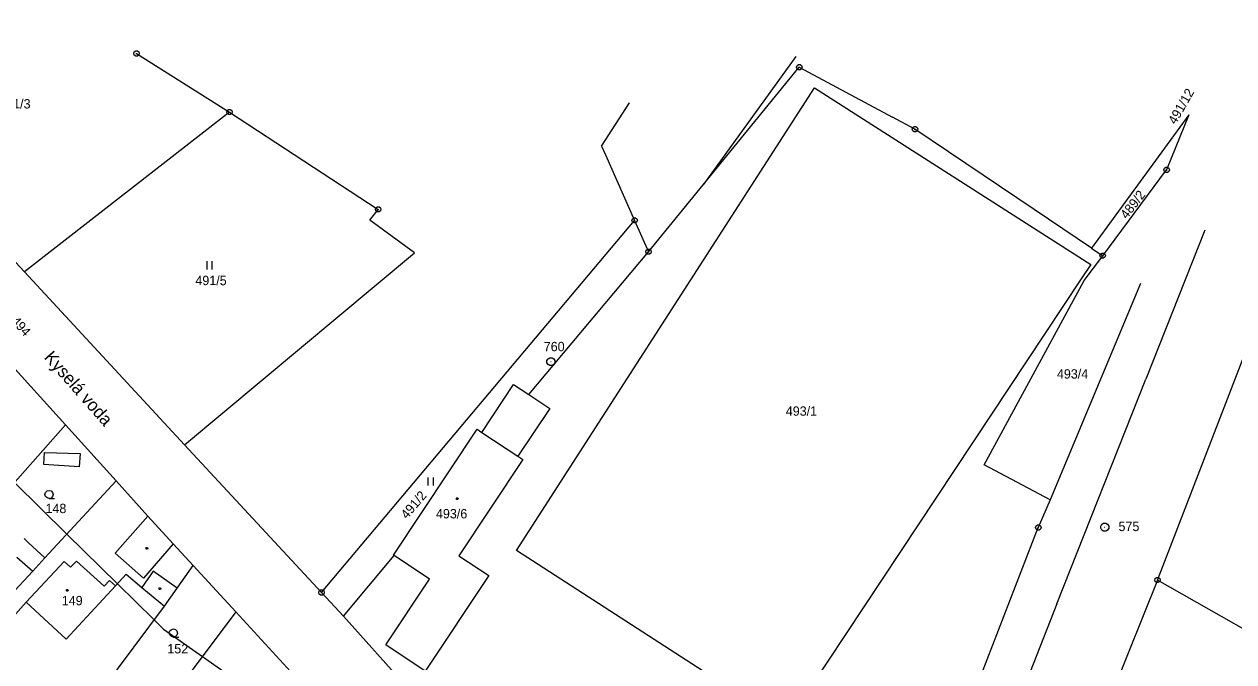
# Model space of a CAD drawing. Extents: x -755359 to -754474, y -1162585 to -1161655.
# Drawn here: x -754872 to -754652.1, y -1161783.9 to -1161668 of the extents above; entities that cross this region are included whole.
import ezdxf

# ---------------------------------------------------------------- set-up
doc = ezdxf.new("R2010")
doc.units = 0
for name, color, linetype in [('Vrstva 1', 7, 'Continuous'), ('Vrstva 11', 7, 'Continuous'), ('Vrstva 12', 7, 'Continuous'), ('Vrstva 2', 7, 'Continuous'), ('Vrstva 3', 7, 'Continuous'), ('Vrstva 4', 7, 'Continuous'), ('Vrstva 5', 7, 'Continuous'), ('Vrstva 6', 7, 'Continuous'), ('Vrstva 7', 7, 'Continuous'), ('Vrstva 8', 7, 'Continuous')]:
    doc.layers.add(name, color=color, linetype=linetype)

msp = doc.modelspace()

# ---------------------------------------------------------------- linework, layer by layer
at = {"layer": 'Vrstva 1'}
for p, q in [((-754871.95, -1161713.02), (-754913.71, -1161667.99)), ((-754851.55, -1161673.34), (-754851.55, -1161673.34)), ((-754851.55, -1161673.34), (-754834.66, -1161683.96)), ((-754731.71, -1161673.87), (-754748.55, -1161697.18)), ((-754748.55, -1161697.18), (-754731.08, -1161675.82)), ((-754731.71, -1161673.87), (-754731.71, -1161673.87)), ((-754731.08, -1161675.82), (-754714.14, -1161684.89)), ((-754767.01, -1161690.15), (-754761.96, -1161682.3)), ((-754761.96, -1161682.3), (-754761.96, -1161682.3)), ((-754834.66, -1161683.96), (-754871.95, -1161713.02)), ((-754834.66, -1161683.96), (-754807.62, -1161701.64)), ((-754660.25, -1161684.48), (-754677.94, -1161708.72)), ((-754660.25, -1161684.48), (-754664.3, -1161694.47)), ((-754660.25, -1161684.48), (-754660.25, -1161684.48)), ((-754714.14, -1161684.89), (-754714.14, -1161684.89)), ((-754710.05, -1161687.08), (-754714.14, -1161684.89)), ((-754703.93, -1161691.21), (-754710.05, -1161687.08)), ((-754767.01, -1161690.15), (-754766.3, -1161691.75)), ((-754703.93, -1161691.21), (-754703.93, -1161691.21)), ((-754688.38, -1161701.69), (-754703.93, -1161691.21)), ((-754766.3, -1161691.75), (-754761.02, -1161703.65)), ((-754766.3, -1161691.75), (-754766.3, -1161691.75)), ((-754675.92, -1161710.08), (-754664.3, -1161694.47)), ((-754664.3, -1161694.47), (-754664.3, -1161694.47)), ((-754758.49, -1161709.34), (-754748.55, -1161697.18)), ((-754809.17, -1161703.58), (-754807.62, -1161701.64)), ((-754688.38, -1161701.69), (-754688.38, -1161701.69)), ((-754677.94, -1161708.72), (-754688.38, -1161701.69)), ((-754817.93, -1161771.28), (-754761.02, -1161703.65)), ((-754801, -1161709.54), (-754809.17, -1161703.58)), ((-754761.02, -1161703.65), (-754758.49, -1161709.34)), ((-754677.94, -1161708.72), (-754677.94, -1161708.72)), ((-754677.94, -1161708.72), (-754675.92, -1161710.08)), ((-754842.82, -1161744.44), (-754801, -1161709.54)), ((-754780.24, -1161735.32), (-754758.49, -1161709.34)), ((-754679.27, -1161714.58), (-754675.92, -1161710.08)), ((-754842.82, -1161744.44), (-754871.95, -1161713.02)), ((-754665.97, -1161769.03), (-754644.01, -1161712.08)), ((-754697.48, -1161748.06), (-754679.27, -1161714.58)), ((-754669.05, -1161715.13), (-754685.45, -1161754.46)), ((-754669.05, -1161715.13), (-754669.05, -1161715.13)), ((-754873.65, -1161730.71), (-754864.46, -1161740.82)), ((-754788.78, -1161742.18), (-754783.01, -1161733.47)), ((-754783.01, -1161733.47), (-754780.24, -1161735.32)), ((-754780.24, -1161735.32), (-754776.44, -1161737.85)), ((-754776.44, -1161737.85), (-754782.27, -1161746.49)), ((-754878.05, -1161756.11), (-754864.46, -1161740.82)), ((-754864.46, -1161740.82), (-754855.27, -1161750.98)), ((-754804.85, -1161764.48), (-754789.63, -1161741.62)), ((-754789.63, -1161741.62), (-754788.78, -1161742.18)), ((-754817.93, -1161771.28), (-754842.82, -1161744.44)), ((-754781.33, -1161747.11), (-754792.96, -1161764.6)), ((-754782.27, -1161746.49), (-754781.33, -1161747.11)), ((-754685.45, -1161754.46), (-754697.48, -1161748.06)), ((-754855.27, -1161750.98), (-754868.2, -1161764.97)), ((-754855.27, -1161750.98), (-754849.48, -1161757.4)), ((-754685.45, -1161754.46), (-754687.63, -1161759.49)), ((-754849.48, -1161757.4), (-754844.87, -1161762.45)), ((-754728.5, -1161864.92), (-754687.63, -1161759.49)), ((-754871.19, -1161762.26), (-754872.01, -1161761.48)), ((-754868.2, -1161764.97), (-754871.19, -1161762.26)), ((-754844.87, -1161762.45), (-754841.27, -1161766.4)), ((-754870.43, -1161767.39), (-754868.2, -1161764.97)), ((-754813.94, -1161775.57), (-754804.72, -1161764.56)), ((-754804.72, -1161764.56), (-754804.85, -1161764.48)), ((-754798.32, -1161768.84), (-754804.72, -1161764.56)), ((-754792.96, -1161764.6), (-754787.53, -1161768.2)), ((-754874.49, -1161771.77), (-754870.43, -1161767.39)), ((-754855.38, -1161770.09), (-754853.46, -1161767.96)), ((-754853.46, -1161767.96), (-754850.61, -1161770.4)), ((-754844.18, -1161770.49), (-754841.27, -1161766.4)), ((-754841.27, -1161766.4), (-754833.48, -1161774.78)), ((-754787.53, -1161768.2), (-754799.07, -1161785.58)), ((-754855.38, -1161770.09), (-754864.38, -1161779.75)), ((-754850.61, -1161770.4), (-754846.5, -1161773.77)), ((-754846.5, -1161773.77), (-754844.18, -1161770.49)), ((-754806.27, -1161780.78), (-754798.32, -1161768.84)), ((-754665.97, -1161769.03), (-754708.18, -1161874.05)), ((-754665.97, -1161769.03), (-754665.97, -1161769.03)), ((-754643.13, -1161782.03), (-754665.97, -1161769.03)), ((-754817.93, -1161771.28), (-754813.94, -1161775.57)), ((-754882.65, -1161785.33), (-754871.6, -1161773.02)), ((-754864.38, -1161779.75), (-754871.6, -1161773.02)), ((-754861.99, -1161794.51), (-754846.5, -1161773.77)), ((-754833.48, -1161774.78), (-754845.76, -1161791.14)), ((-754833.48, -1161774.78), (-754823.5, -1161785.69)), ((-754813.94, -1161775.57), (-754776.63, -1161817.12)), ((-754799.07, -1161785.58), (-754806.27, -1161780.78))]:
    msp.add_line(p, q, dxfattribs=at)
at = {"layer": 'Vrstva 11'}
for p, q in [((-754873.75, -1161751.27), (-754864.21, -1161760.65)), ((-754864.21, -1161760.65), (-754855.03, -1161769.7)), ((-754855.03, -1161769.7), (-754848.36, -1161776.26)), ((-754848.36, -1161776.26), (-754846.65, -1161777.95)), ((-754846.65, -1161777.95), (-754839.58, -1161782.9)), ((-754839.58, -1161782.9), (-754834.21, -1161786.66))]:
    msp.add_line(p, q, dxfattribs=at)
at = {"layer": 'Vrstva 12'}
for p, q in [((-754804.85, -1161764.48), (-754789.63, -1161741.62)), ((-754789.63, -1161741.62), (-754788.78, -1161742.18)), ((-754788.78, -1161742.18), (-754782.27, -1161746.49)), ((-754781.33, -1161747.11), (-754792.96, -1161764.6)), ((-754782.27, -1161746.49), (-754781.33, -1161747.11)), ((-754871.6, -1161773.02), (-754864.69, -1161765.63)), ((-754864.69, -1161765.63), (-754863.57, -1161766.68)), ((-754863.57, -1161766.68), (-754862.5, -1161765.56)), ((-754862.5, -1161765.56), (-754857.43, -1161770.14)), ((-754804.72, -1161764.56), (-754804.85, -1161764.48)), ((-754798.32, -1161768.84), (-754804.72, -1161764.56)), ((-754792.96, -1161764.6), (-754787.53, -1161768.2)), ((-754787.53, -1161768.2), (-754799.07, -1161785.58)), ((-754855.38, -1161770.09), (-754864.38, -1161779.75)), ((-754857.43, -1161770.14), (-754856.47, -1161769.09)), ((-754856.47, -1161769.09), (-754855.38, -1161770.09)), ((-754806.27, -1161780.78), (-754798.32, -1161768.84)), ((-754864.38, -1161779.75), (-754871.6, -1161773.02)), ((-754799.07, -1161785.58), (-754806.27, -1161780.78))]:
    msp.add_line(p, q, dxfattribs=at)
at = {"layer": 'Vrstva 3'}
for p, q in [((-754838.78, -1161711.08), (-754838.78, -1161712.58)), ((-754837.78, -1161712.58), (-754837.78, -1161711.08)), ((-754798.6, -1161750.35), (-754798.6, -1161751.85)), ((-754797.6, -1161751.85), (-754797.6, -1161750.35))]:
    msp.add_line(p, q, dxfattribs=at)
for points in [[(-754867.45, -1161754.2), (-754867.83, -1161754.1), (-754868.1, -1161753.83), (-754868.2, -1161753.46), (-754868.1, -1161753.09), (-754867.83, -1161752.82), (-754867.46, -1161752.72), (-754867.09, -1161752.82), (-754866.82, -1161753.09), (-754866.72, -1161753.47), (-754866.82, -1161753.85), (-754867.09, -1161754.12), (-754867.47, -1161754.22), (-754866.47, -1161754.22)], [(-754844.85, -1161779.37), (-754845.23, -1161779.27), (-754845.5, -1161779), (-754845.6, -1161778.63), (-754845.5, -1161778.26), (-754845.23, -1161777.99), (-754844.86, -1161777.89), (-754844.49, -1161777.99), (-754844.22, -1161778.26), (-754844.12, -1161778.64), (-754844.22, -1161779.02), (-754844.49, -1161779.29), (-754844.87, -1161779.39), (-754843.87, -1161779.39)]]:
    msp.add_lwpolyline(points, dxfattribs=at)
at = {"layer": 'Vrstva 4'}
for p, q in [((-754782.49, -1161763.64), (-754728.32, -1161679.57)), ((-754728.32, -1161679.57), (-754678.1, -1161711.64)), ((-754678.1, -1161711.64), (-754679.82, -1161714.24)), ((-754679.82, -1161714.24), (-754733.53, -1161795.26)), ((-754788.78, -1161742.18), (-754782.27, -1161746.49)), ((-754868.42, -1161747.99), (-754868.3, -1161745.81)), ((-754868.3, -1161745.81), (-754861.81, -1161746.01)), ((-754861.81, -1161746.01), (-754862, -1161748.41)), ((-754862, -1161748.41), (-754868.42, -1161747.99)), ((-754855.45, -1161764.13), (-754849.48, -1161757.4)), ((-754844.87, -1161762.45), (-754850.27, -1161768.69)), ((-754733.53, -1161795.26), (-754782.49, -1161763.64)), ((-754873.32, -1161764.86), (-754870.43, -1161767.39)), ((-754871.6, -1161773.02), (-754864.69, -1161765.63)), ((-754864.69, -1161765.63), (-754863.57, -1161766.68)), ((-754863.57, -1161766.68), (-754862.5, -1161765.56)), ((-754862.5, -1161765.56), (-754857.43, -1161770.14)), ((-754850.27, -1161768.69), (-754855.45, -1161764.13)), ((-754848.51, -1161767.42), (-754850.61, -1161770.4)), ((-754844.18, -1161770.49), (-754848.51, -1161767.42)), ((-754857.43, -1161770.14), (-754856.47, -1161769.09)), ((-754856.47, -1161769.09), (-754855.38, -1161770.09))]:
    msp.add_line(p, q, dxfattribs=at)
at = {"layer": 'Vrstva 5'}
for points in [[(-754793.16, -1161754.06), (-754793.07, -1161754.21), (-754793.16, -1161754.36), (-754793.34, -1161754.36), (-754793.43, -1161754.21), (-754793.34, -1161754.06)], [(-754849.57, -1161763.13), (-754849.48, -1161763.28), (-754849.57, -1161763.43), (-754849.75, -1161763.43), (-754849.84, -1161763.28), (-754849.75, -1161763.13)], [(-754847.23, -1161770.46), (-754847.14, -1161770.61), (-754847.23, -1161770.76), (-754847.41, -1161770.76), (-754847.5, -1161770.61), (-754847.41, -1161770.46)], [(-754864.07, -1161770.76), (-754863.98, -1161770.91), (-754864.07, -1161771.06), (-754864.25, -1161771.06), (-754864.34, -1161770.91), (-754864.25, -1161770.76)]]:
    msp.add_lwpolyline(points, close=True, dxfattribs=at)
at = {"layer": 'Vrstva 6'}
for p, q in [((-754657.36, -1161705.45), (-754668.08, -1161732.53)), ((-754657.36, -1161705.45), (-754657.36, -1161705.45)), ((-754684.25, -1161773.32), (-754668.08, -1161732.53)), ((-754684.25, -1161773.32), (-754736, -1161904.52))]:
    msp.add_line(p, q, dxfattribs=at)
at = {"layer": 'Vrstva 8'}
for p, q in [((-754851.67, -1161673.34), (-754851.43, -1161673.34)), ((-754731.2, -1161675.82), (-754730.96, -1161675.82)), ((-754834.78, -1161683.96), (-754834.54, -1161683.96)), ((-754710.17, -1161687.08), (-754709.93, -1161687.08)), ((-754664.42, -1161694.47), (-754664.18, -1161694.47)), ((-754807.74, -1161701.64), (-754807.5, -1161701.64)), ((-754761.14, -1161703.65), (-754760.9, -1161703.65)), ((-754758.61, -1161709.34), (-754758.37, -1161709.34)), ((-754676.04, -1161710.08), (-754675.8, -1161710.08)), ((-754776.27, -1161729.32), (-754776.17, -1161729.32)), ((-754687.75, -1161759.49), (-754687.51, -1161759.49)), ((-754675.61, -1161759.41), (-754675.51, -1161759.41)), ((-754666.09, -1161769.03), (-754665.85, -1161769.03)), ((-754818.05, -1161771.28), (-754817.81, -1161771.28))]:
    msp.add_line(p, q, dxfattribs=at)
for points in [[(-754851.4, -1161672.86), (-754851.15, -1161673.04), (-754851.05, -1161673.33), (-754851.15, -1161673.62), (-754851.4, -1161673.8), (-754851.71, -1161673.8), (-754851.96, -1161673.62), (-754852.06, -1161673.33), (-754851.96, -1161673.04), (-754851.71, -1161672.86)], [(-754730.93, -1161675.34), (-754730.68, -1161675.52), (-754730.58, -1161675.81), (-754730.68, -1161676.1), (-754730.93, -1161676.28), (-754731.24, -1161676.28), (-754731.49, -1161676.1), (-754731.59, -1161675.81), (-754731.49, -1161675.52), (-754731.24, -1161675.34)], [(-754834.51, -1161683.48), (-754834.26, -1161683.66), (-754834.16, -1161683.95), (-754834.26, -1161684.24), (-754834.51, -1161684.42), (-754834.82, -1161684.42), (-754835.07, -1161684.24), (-754835.17, -1161683.95), (-754835.07, -1161683.66), (-754834.82, -1161683.48)], [(-754709.9, -1161686.6), (-754709.65, -1161686.78), (-754709.55, -1161687.07), (-754709.65, -1161687.36), (-754709.9, -1161687.54), (-754710.21, -1161687.54), (-754710.46, -1161687.36), (-754710.56, -1161687.07), (-754710.46, -1161686.78), (-754710.21, -1161686.6)], [(-754664.15, -1161693.99), (-754663.9, -1161694.17), (-754663.8, -1161694.46), (-754663.9, -1161694.75), (-754664.15, -1161694.93), (-754664.46, -1161694.93), (-754664.71, -1161694.75), (-754664.81, -1161694.46), (-754664.71, -1161694.17), (-754664.46, -1161693.99)], [(-754807.47, -1161701.16), (-754807.22, -1161701.34), (-754807.12, -1161701.63), (-754807.22, -1161701.92), (-754807.47, -1161702.1), (-754807.78, -1161702.1), (-754808.03, -1161701.92), (-754808.13, -1161701.63), (-754808.03, -1161701.34), (-754807.78, -1161701.16)], [(-754760.87, -1161703.17), (-754760.62, -1161703.35), (-754760.52, -1161703.64), (-754760.62, -1161703.93), (-754760.87, -1161704.11), (-754761.18, -1161704.11), (-754761.43, -1161703.93), (-754761.53, -1161703.64), (-754761.43, -1161703.35), (-754761.18, -1161703.17)], [(-754758.34, -1161708.86), (-754758.09, -1161709.04), (-754757.99, -1161709.33), (-754758.09, -1161709.62), (-754758.34, -1161709.8), (-754758.65, -1161709.8), (-754758.9, -1161709.62), (-754759, -1161709.33), (-754758.9, -1161709.04), (-754758.65, -1161708.86)], [(-754675.77, -1161709.6), (-754675.52, -1161709.78), (-754675.42, -1161710.07), (-754675.52, -1161710.36), (-754675.77, -1161710.54), (-754676.08, -1161710.54), (-754676.33, -1161710.36), (-754676.43, -1161710.07), (-754676.33, -1161709.78), (-754676.08, -1161709.6)], [(-754776.03, -1161728.6), (-754775.69, -1161728.79), (-754775.5, -1161729.13), (-754775.5, -1161729.52), (-754775.69, -1161729.86), (-754776.03, -1161730.05), (-754776.42, -1161730.05), (-754776.76, -1161729.86), (-754776.95, -1161729.52), (-754776.95, -1161729.13), (-754776.76, -1161728.79), (-754776.42, -1161728.6)], [(-754687.48, -1161759.01), (-754687.23, -1161759.19), (-754687.13, -1161759.48), (-754687.23, -1161759.77), (-754687.48, -1161759.95), (-754687.79, -1161759.95), (-754688.04, -1161759.77), (-754688.14, -1161759.48), (-754688.04, -1161759.19), (-754687.79, -1161759.01)], [(-754675.37, -1161758.69), (-754675.03, -1161758.88), (-754674.84, -1161759.22), (-754674.84, -1161759.61), (-754675.03, -1161759.95), (-754675.37, -1161760.14), (-754675.76, -1161760.14), (-754676.1, -1161759.95), (-754676.29, -1161759.61), (-754676.29, -1161759.22), (-754676.1, -1161758.88), (-754675.76, -1161758.69)], [(-754665.82, -1161768.55), (-754665.57, -1161768.73), (-754665.47, -1161769.02), (-754665.57, -1161769.31), (-754665.82, -1161769.49), (-754666.13, -1161769.49), (-754666.38, -1161769.31), (-754666.48, -1161769.02), (-754666.38, -1161768.73), (-754666.13, -1161768.55)], [(-754817.78, -1161770.8), (-754817.53, -1161770.98), (-754817.43, -1161771.27), (-754817.53, -1161771.56), (-754817.78, -1161771.74), (-754818.09, -1161771.74), (-754818.34, -1161771.56), (-754818.44, -1161771.27), (-754818.34, -1161770.98), (-754818.09, -1161770.8)]]:
    msp.add_lwpolyline(points, close=True, dxfattribs=at)

# ---------------------------------------------------------------- texts
at = {"layer": 'Vrstva 2'}
for s, rotation, p in [('491/12', 60.27516, (-754662.672, -1161686.344)), ('489/2', 52.19646, (-754671.544, -1161703.522)), ('494', 311.40256, (-754874.423, -1161722.018)), ('491/2', 49.50355, (-754802.406, -1161758.049))]:
    msp.add_text(s, height=1.7, rotation=rotation, dxfattribs=at).set_placement(p)
for s, p in [('491/3', (-754876.513, -1161683.31)), ('491/5', (-754840.863, -1161715.42)), ('493/4', (-754684.253, -1161732.4)), ('493/1', (-754733.533, -1161739.15)), ('148', (-754868.107, -1161756.85)), ('493/6', (-754797.13, -1161757.81)), ('149', (-754865.147, -1161773.6)), ('152', (-754845.967, -1161782.35))]:
    msp.add_text(s, height=1.7, dxfattribs=at).set_placement(p)
at = {"layer": 'Vrstva 7'}
msp.add_text('Kyselá voda', height=2.3, rotation=311.40256, dxfattribs=at).set_placement((-754868.491, -1161728.632))
at = {"layer": 'Vrstva 8'}
for s, p in [('760', (-754777.533, -1161727.43)), ('575', (-754673.053, -1161760.12))]:
    msp.add_text(s, height=1.7, dxfattribs=at).set_placement(p)

doc.saveas('drawing.dxf')
